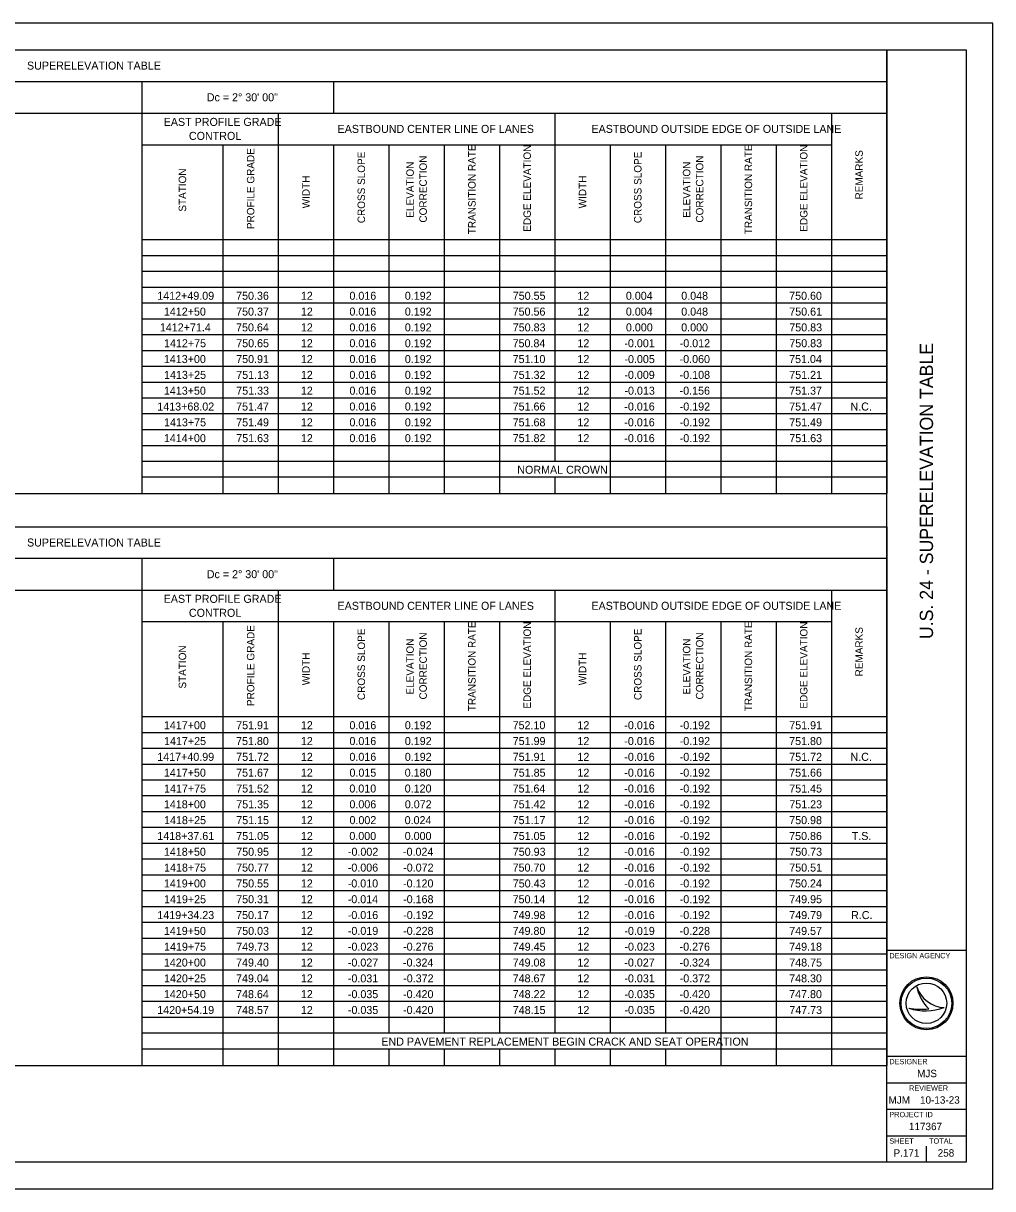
# Model space of a CAD drawing. Extents: x 0 to 34, y 0 to 22.
# Drawn here: x 15.71 to 34, y 0 to 22 of the extents above; entities that cross this region are included whole.
import ezdxf

# ---------------------------------------------------------------- set-up
doc = ezdxf.new("R2010")
doc.units = 0
for name, color, linetype in [('Default', 7, 'Continuous'), ('SH_Border', 7, 'Continuous'), ('SH_Cut_Line', 7, 'Continuous'), ('SH_Data', 7, 'Continuous')]:
    doc.layers.add(name, color=color, linetype=linetype)

msp = doc.modelspace()

# ---------------------------------------------------------------- linework, layer by layer
at = {"layer": 'Default'}
for p, q in [((1.5, 21.5), (32, 21.5)), ((32, 21.5), (32, 13.122)), ((1.5, 20.903), (32, 20.903)), ((17.947, 20.903), (17.947, 13.122)), ((21.564, 20.903), (21.564, 20.305)), ((1.5, 20.305), (32, 20.305)), ((20.521, 20.305), (20.521, 17.916)), ((25.739, 20.305), (25.739, 17.916)), ((30.956, 20.305), (30.956, 17.916)), ((17.947, 19.708), (30.956, 19.708)), ((19.477, 19.708), (19.477, 17.916)), ((21.564, 19.708), (21.564, 17.916)), ((22.608, 19.708), (22.608, 17.916)), ((23.651, 19.708), (23.651, 17.916)), ((24.695, 19.708), (24.695, 17.916)), ((26.782, 19.708), (26.782, 17.916)), ((27.826, 19.708), (27.826, 17.916)), ((28.869, 19.708), (28.869, 17.916)), ((29.913, 19.708), (29.913, 17.916)), ((17.947, 17.916), (32, 17.916)), ((19.477, 17.916), (19.477, 13.122)), ((20.521, 17.916), (20.521, 13.122)), ((21.564, 17.916), (21.564, 13.122)), ((22.608, 17.916), (22.608, 13.122)), ((23.651, 17.916), (23.651, 13.122)), ((24.695, 17.916), (24.695, 13.122)), ((25.739, 17.916), (25.739, 13.735)), ((26.782, 17.916), (26.782, 13.122)), ((27.826, 17.916), (27.826, 13.122)), ((28.869, 17.916), (28.869, 13.122)), ((29.913, 17.916), (29.913, 13.122)), ((30.956, 17.916), (30.956, 13.122)), ((17.947, 17.617), (32, 17.617)), ((17.947, 17.319), (32, 17.319)), ((17.947, 17.02), (32, 17.02)), ((17.947, 16.721), (32, 16.721)), ((17.947, 16.423), (32, 16.423)), ((17.947, 16.124), (32, 16.124)), ((17.947, 15.825), (32, 15.825)), ((17.947, 15.527), (32, 15.527)), ((17.947, 15.228), (32, 15.228)), ((17.947, 14.929), (32, 14.929)), ((17.947, 14.631), (32, 14.631)), ((17.947, 14.332), (32, 14.332)), ((17.947, 14.033), (32, 14.033)), ((17.947, 13.735), (32, 13.735)), ((17.947, 13.436), (32, 13.436)), ((25.739, 13.436), (25.739, 13.122)), ((1.5, 13.122), (32, 13.122)), ((1.5, 12.497), (32, 12.497)), ((32, 12.497), (32, 2.327)), ((1.5, 11.9), (32, 11.9)), ((17.947, 11.9), (17.947, 2.327)), ((21.564, 11.9), (21.564, 11.302)), ((1.5, 11.302), (32, 11.302)), ((20.521, 11.302), (20.521, 8.913)), ((25.739, 11.302), (25.739, 8.913)), ((30.956, 11.302), (30.956, 8.913)), ((17.947, 10.705), (30.956, 10.705)), ((19.477, 10.705), (19.477, 8.913)), ((21.564, 10.705), (21.564, 8.913)), ((22.608, 10.705), (22.608, 8.913)), ((23.651, 10.705), (23.651, 8.913)), ((24.695, 10.705), (24.695, 8.913)), ((26.782, 10.705), (26.782, 8.913)), ((27.826, 10.705), (27.826, 8.913)), ((28.869, 10.705), (28.869, 8.913)), ((29.913, 10.705), (29.913, 8.913)), ((17.947, 8.913), (32, 8.913)), ((19.477, 8.913), (19.477, 2.327)), ((20.521, 8.913), (20.521, 2.327)), ((21.564, 8.913), (21.564, 2.327)), ((22.608, 8.913), (22.608, 2.94)), ((23.651, 8.913), (23.651, 2.94)), ((24.695, 8.913), (24.695, 2.94)), ((25.739, 8.913), (25.739, 2.94)), ((26.782, 8.913), (26.782, 2.94)), ((27.826, 8.913), (27.826, 2.94)), ((28.869, 8.913), (28.869, 2.327)), ((29.913, 8.913), (29.913, 2.327)), ((30.956, 8.913), (30.956, 2.327)), ((17.947, 8.614), (32, 8.614)), ((17.947, 8.316), (32, 8.316)), ((17.947, 8.017), (32, 8.017)), ((17.947, 7.718), (32, 7.718)), ((17.947, 7.42), (32, 7.42)), ((17.947, 7.121), (32, 7.121)), ((17.947, 6.822), (32, 6.822)), ((17.947, 6.524), (32, 6.524)), ((17.947, 6.225), (32, 6.225)), ((17.947, 5.926), (32, 5.926)), ((17.947, 5.628), (32, 5.628)), ((17.947, 5.329), (32, 5.329)), ((17.947, 5.03), (32, 5.03)), ((17.947, 4.732), (32, 4.732)), ((17.947, 4.433), (32, 4.433)), ((17.947, 4.134), (32, 4.134)), ((17.947, 3.836), (32, 3.836)), ((17.947, 3.537), (32, 3.537)), ((17.947, 3.238), (32, 3.238)), ((17.947, 2.94), (32, 2.94)), ((17.947, 2.641), (32, 2.641)), ((22.608, 2.641), (22.608, 2.327)), ((23.651, 2.641), (23.651, 2.327)), ((24.695, 2.641), (24.695, 2.327)), ((25.739, 2.641), (25.739, 2.327)), ((26.782, 2.641), (26.782, 2.327)), ((27.826, 2.641), (27.826, 2.327)), ((1.5, 2.327), (32, 2.327))]:
    msp.add_line(p, q, dxfattribs=at)
at = {"layer": 'SH_Border'}
for p, q in [((32, 0.5), (32, 21.5)), ((32, 4.5), (33.5, 4.5)), ((32, 2.5), (33.5, 2.5)), ((32, 2), (33.5, 2)), ((32, 1.5), (33.5, 1.5)), ((32, 1), (33.5, 1))]:
    msp.add_line(p, q, dxfattribs=at)
msp.add_lwpolyline([(1.5, 21.5), (33.5, 21.5), (33.5, 0.5), (1.5, 0.5)], close=True, dxfattribs=at)
at = {"layer": 'SH_Cut_Line'}
msp.add_lwpolyline([(0, 0), (34, 0), (34, 22), (0, 22)], close=True, dxfattribs=at)
at = {"layer": 'SH_Data'}
for p, q in [((32.567, 3.81), (32.567, 3.81)), ((32.417, 3.41), (32.417, 3.41)), ((32.75, 3.5), (32.75, 3.5)), ((33.087, 3.419), (33.087, 3.419)), ((32.375, 0.675), (32.375, 0.675)), ((32.75, 0.5), (32.75, 0.8))]:
    msp.add_line(p, q, dxfattribs=at)
for radius in [0.5, 0.477, 0.477, 0.382]:
    msp.add_circle((32.75, 3.5), radius, dxfattribs=at)
for centre, radius, start, end in [((33.116, 3.998), 0.58, 198.9257, 198.9319), ((33.347, 3.97), 0.796, 191.6379, 191.6421), ((33.116, 3.998), 0.58, 198.9319, 267.1657), ((33.347, 3.97), 0.796, 191.6421, 226.0947), ((32.739, 4.37), 1.013, 251.4576, 290.0832), ((32.648, 4.654), 1.266, 259.4964, 259.4995), ((32.739, 4.37), 1.013, 251.4527, 251.4576), ((32.648, 4.654), 1.266, 259.4995, 276.6672)]:
    msp.add_arc(centre, radius, start, end, dxfattribs=at)

# ---------------------------------------------------------------- texts
at = {"layer": 'Default'}
for s, height, p in [('SUPERELEVATION TABLE', 0.15112, (15.779, 21.126)), ('Dc = 2° 30\' 00"', 0.15112, (19.171, 20.528)), ('EAST PROFILE GRADE ', 0.15112, (18.358, 20.063)), ('EASTBOUND CENTER LINE OF LANES', 0.15112, (21.639, 19.931)), ('EASTBOUND OUTSIDE EDGE OF OUTSIDE LANE', 0.15112, (26.429, 19.931)), ('CONTROL', 0.1511, (18.834, 19.799)), ('1412+49.09', 0.1511, (18.237, 16.781)), ('750.36', 0.1511, (19.725, 16.781)), ('12', 0.1511, (20.947, 16.781)), ('0.016', 0.1511, (21.863, 16.781)), ('0.192', 0.1511, (22.908, 16.781)), ('750.55', 0.1511, (24.945, 16.781)), ('12', 0.1511, (26.165, 16.781)), ('0.004', 0.1511, (27.079, 16.781)), ('0.048', 0.1511, (28.124, 16.781)), ('750.60', 0.1511, (30.16, 16.781)), ('1412+50', 0.1511, (18.362, 16.482)), ('750.37', 0.1511, (19.725, 16.482)), ('12', 0.1511, (20.947, 16.482)), ('0.016', 0.1511, (21.863, 16.482)), ('0.192', 0.1511, (22.908, 16.482)), ('750.56', 0.1511, (24.943, 16.482)), ('12', 0.1511, (26.165, 16.482)), ('0.004', 0.1511, (27.079, 16.482)), ('0.048', 0.1511, (28.124, 16.482)), ('750.61', 0.1511, (30.162, 16.482)), ('1412+71.4', 0.1511, (18.286, 16.184)), ('750.64', 0.1511, (19.724, 16.184)), ('12', 0.1511, (20.947, 16.184)), ('0.016', 0.1511, (21.863, 16.184)), ('0.192', 0.1511, (22.908, 16.184)), ('750.83', 0.1511, (24.945, 16.184)), ('12', 0.1511, (26.165, 16.184)), ('0.000', 0.1511, (27.08, 16.184)), ('0.000', 0.1511, (28.123, 16.184)), ('750.83', 0.1511, (30.163, 16.184)), ('1412+75', 0.1511, (18.365, 15.885)), ('750.65', 0.1511, (19.727, 15.885)), ('12', 0.1511, (20.947, 15.885)), ('0.016', 0.1511, (21.863, 15.885)), ('0.192', 0.1511, (22.908, 15.885)), ('750.84', 0.1511, (24.942, 15.885)), ('12', 0.1511, (26.165, 15.885)), ('-0.001', 0.1511, (27.051, 15.885)), ('-0.012', 0.1511, (28.095, 15.885)), ('750.83', 0.1511, (30.163, 15.885)), ('1413+00', 0.1511, (18.362, 15.586)), ('750.91', 0.1511, (19.726, 15.586)), ('12', 0.1511, (20.947, 15.586)), ('0.016', 0.1511, (21.863, 15.586)), ('0.192', 0.1511, (22.908, 15.586)), ('751.10', 0.1511, (24.942, 15.586)), ('12', 0.1511, (26.165, 15.586)), ('-0.005', 0.1511, (27.052, 15.586)), ('-0.060', 0.1511, (28.093, 15.586)), ('751.04', 0.1511, (30.159, 15.586)), ('1413+25', 0.1511, (18.365, 15.288)), ('751.13', 0.1511, (19.727, 15.288)), ('12', 0.1511, (20.947, 15.288)), ('0.016', 0.1511, (21.863, 15.288)), ('0.192', 0.1511, (22.908, 15.288)), ('751.32', 0.1511, (24.944, 15.288)), ('12', 0.1511, (26.165, 15.288)), ('-0.009', 0.1511, (27.051, 15.288)), ('-0.108', 0.1511, (28.094, 15.288)), ('751.21', 0.1511, (30.162, 15.288)), ('1413+50', 0.1511, (18.362, 14.989)), ('751.33', 0.1511, (19.727, 14.989)), ('12', 0.1511, (20.947, 14.989)), ('0.016', 0.1511, (21.863, 14.989)), ('0.192', 0.1511, (22.908, 14.989)), ('751.52', 0.1511, (24.944, 14.989)), ('12', 0.1511, (26.165, 14.989)), ('-0.013', 0.1511, (27.052, 14.989)), ('-0.156', 0.1511, (28.093, 14.989)), ('751.37', 0.1511, (30.161, 14.989)), ('1413+68.02', 0.1511, (18.238, 14.69)), ('751.47', 0.1511, (19.725, 14.69)), ('12', 0.1511, (20.947, 14.69)), ('0.016', 0.1511, (21.863, 14.69)), ('0.192', 0.1511, (22.908, 14.69)), ('751.66', 0.1511, (24.943, 14.69)), ('12', 0.1511, (26.165, 14.69)), ('-0.016', 0.1511, (27.05, 14.69)), ('-0.192', 0.1511, (28.095, 14.69)), ('751.47', 0.1511, (30.161, 14.69)), ('N.C.', 0.1511, (31.317, 14.69)), ('1413+75', 0.1511, (18.365, 14.392)), ('751.49', 0.1511, (19.726, 14.392)), ('12', 0.1511, (20.947, 14.392)), ('0.016', 0.1511, (21.863, 14.392)), ('0.192', 0.1511, (22.908, 14.392)), ('751.68', 0.1511, (24.943, 14.392)), ('12', 0.1511, (26.165, 14.392)), ('-0.016', 0.1511, (27.05, 14.392)), ('-0.192', 0.1511, (28.095, 14.392)), ('751.49', 0.1511, (30.162, 14.392)), ('1414+00', 0.1511, (18.362, 14.093)), ('751.63', 0.1511, (19.727, 14.093)), ('12', 0.1511, (20.947, 14.093)), ('0.016', 0.1511, (21.863, 14.093)), ('0.192', 0.1511, (22.908, 14.093)), ('751.82', 0.1511, (24.944, 14.093)), ('12', 0.1511, (26.165, 14.093)), ('-0.016', 0.1511, (27.05, 14.093)), ('-0.192', 0.1511, (28.095, 14.093)), ('751.63', 0.1511, (30.163, 14.093)), ('NORMAL CROWN', 0.15112, (25.03, 13.496)), ('SUPERELEVATION TABLE', 0.15112, (15.779, 12.123)), ('Dc = 2° 30\' 00"', 0.15112, (19.171, 11.525)), ('EAST PROFILE GRADE ', 0.15112, (18.358, 11.06)), ('EASTBOUND CENTER LINE OF LANES', 0.15112, (21.639, 10.928)), ('EASTBOUND OUTSIDE EDGE OF OUTSIDE LANE', 0.15112, (26.429, 10.928)), ('CONTROL', 0.1511, (18.834, 10.796)), ('1417+00', 0.1511, (18.362, 8.674)), ('751.91', 0.1511, (19.726, 8.674)), ('12', 0.1511, (20.947, 8.674)), ('0.016', 0.1511, (21.863, 8.674)), ('0.192', 0.1511, (22.908, 8.674)), ('752.10', 0.1511, (24.942, 8.674)), ('12', 0.1511, (26.165, 8.674)), ('-0.016', 0.1511, (27.05, 8.674)), ('-0.192', 0.1511, (28.095, 8.674)), ('751.91', 0.1511, (30.162, 8.674)), ('1417+25', 0.1511, (18.365, 8.375)), ('751.80', 0.1511, (19.724, 8.375)), ('12', 0.1511, (20.947, 8.375)), ('0.016', 0.1511, (21.863, 8.375)), ('0.192', 0.1511, (22.908, 8.375)), ('751.99', 0.1511, (24.944, 8.375)), ('12', 0.1511, (26.165, 8.375)), ('-0.016', 0.1511, (27.05, 8.375)), ('-0.192', 0.1511, (28.095, 8.375)), ('751.80', 0.1511, (30.16, 8.375)), ('1417+40.99', 0.1511, (18.237, 8.077)), ('751.72', 0.1511, (19.726, 8.077)), ('12', 0.1511, (20.947, 8.077)), ('0.016', 0.1511, (21.863, 8.077)), ('0.192', 0.1511, (22.908, 8.077)), ('751.91', 0.1511, (24.944, 8.077)), ('12', 0.1511, (26.165, 8.077)), ('-0.016', 0.1511, (27.05, 8.077)), ('-0.192', 0.1511, (28.095, 8.077)), ('751.72', 0.1511, (30.162, 8.077)), ('N.C.', 0.1511, (31.317, 8.077)), ('1417+50', 0.1511, (18.362, 7.778)), ('751.67', 0.1511, (19.725, 7.778)), ('12', 0.1511, (20.947, 7.778)), ('0.015', 0.1511, (21.864, 7.778)), ('0.180', 0.1511, (22.906, 7.778)), ('751.85', 0.1511, (24.945, 7.778)), ('12', 0.1511, (26.165, 7.778)), ('-0.016', 0.1511, (27.05, 7.778)), ('-0.192', 0.1511, (28.095, 7.778)), ('751.66', 0.1511, (30.16, 7.778)), ('1417+75', 0.1511, (18.365, 7.479)), ('751.52', 0.1511, (19.726, 7.479)), ('12', 0.1511, (20.947, 7.479)), ('0.010', 0.1511, (21.862, 7.479)), ('0.120', 0.1511, (22.906, 7.479)), ('751.64', 0.1511, (24.942, 7.479)), ('12', 0.1511, (26.165, 7.479)), ('-0.016', 0.1511, (27.05, 7.479)), ('-0.192', 0.1511, (28.095, 7.479)), ('751.45', 0.1511, (30.162, 7.479)), ('1418+00', 0.1511, (18.362, 7.181)), ('751.35', 0.1511, (19.727, 7.181)), ('12', 0.1511, (20.947, 7.181)), ('0.006', 0.1511, (21.863, 7.181)), ('0.072', 0.1511, (22.908, 7.181)), ('751.42', 0.1511, (24.944, 7.181)), ('12', 0.1511, (26.165, 7.181)), ('-0.016', 0.1511, (27.05, 7.181)), ('-0.192', 0.1511, (28.095, 7.181)), ('751.23', 0.1511, (30.163, 7.181)), ('1418+25', 0.1511, (18.365, 6.882)), ('751.15', 0.1511, (19.727, 6.882)), ('12', 0.1511, (20.947, 6.882)), ('0.002', 0.1511, (21.864, 6.882)), ('0.024', 0.1511, (22.905, 6.882)), ('751.17', 0.1511, (24.943, 6.882)), ('12', 0.1511, (26.165, 6.882)), ('-0.016', 0.1511, (27.05, 6.882)), ('-0.192', 0.1511, (28.095, 6.882)), ('750.98', 0.1511, (30.161, 6.882)), ('1418+37.61', 0.1511, (18.238, 6.583)), ('751.05', 0.1511, (19.727, 6.583)), ('12', 0.1511, (20.947, 6.583)), ('0.000', 0.1511, (21.862, 6.583)), ('0.000', 0.1511, (22.906, 6.583)), ('751.05', 0.1511, (24.945, 6.583)), ('12', 0.1511, (26.165, 6.583)), ('-0.016', 0.1511, (27.05, 6.583)), ('-0.192', 0.1511, (28.095, 6.583)), ('750.86', 0.1511, (30.16, 6.583)), ('T.S.', 0.1511, (31.341, 6.583)), ('1418+50', 0.1511, (18.362, 6.285)), ('750.95', 0.1511, (19.727, 6.285)), ('12', 0.1511, (20.947, 6.285)), ('-0.002', 0.1511, (21.834, 6.285)), ('-0.024', 0.1511, (22.874, 6.285)), ('750.93', 0.1511, (24.945, 6.285)), ('12', 0.1511, (26.165, 6.285)), ('-0.016', 0.1511, (27.05, 6.285)), ('-0.192', 0.1511, (28.095, 6.285)), ('750.73', 0.1511, (30.163, 6.285)), ('1418+75', 0.1511, (18.365, 5.986)), ('750.77', 0.1511, (19.725, 5.986)), ('12', 0.1511, (20.947, 5.986)), ('-0.006', 0.1511, (21.832, 5.986)), ('-0.072', 0.1511, (22.877, 5.986)), ('750.70', 0.1511, (24.942, 5.986)), ('12', 0.1511, (26.165, 5.986)), ('-0.016', 0.1511, (27.05, 5.986)), ('-0.192', 0.1511, (28.095, 5.986)), ('750.51', 0.1511, (30.162, 5.986)), ('1419+00', 0.1511, (18.362, 5.687)), ('750.55', 0.1511, (19.727, 5.687)), ('12', 0.1511, (20.947, 5.687)), ('-0.010', 0.1511, (21.831, 5.687)), ('-0.120', 0.1511, (22.875, 5.687)), ('750.43', 0.1511, (24.945, 5.687)), ('12', 0.1511, (26.165, 5.687)), ('-0.016', 0.1511, (27.05, 5.687)), ('-0.192', 0.1511, (28.095, 5.687)), ('750.24', 0.1511, (30.159, 5.687)), ('1419+25', 0.1511, (18.365, 5.389)), ('750.31', 0.1511, (19.726, 5.389)), ('12', 0.1511, (20.947, 5.389)), ('-0.014', 0.1511, (21.831, 5.389)), ('-0.168', 0.1511, (22.876, 5.389)), ('750.14', 0.1511, (24.942, 5.389)), ('12', 0.1511, (26.165, 5.389)), ('-0.016', 0.1511, (27.05, 5.389)), ('-0.192', 0.1511, (28.095, 5.389)), ('749.95', 0.1511, (30.162, 5.389)), ('1419+34.23', 0.1511, (18.238, 5.09)), ('750.17', 0.1511, (19.725, 5.09)), ('12', 0.1511, (20.947, 5.09)), ('-0.016', 0.1511, (21.832, 5.09)), ('-0.192', 0.1511, (22.877, 5.09)), ('749.98', 0.1511, (24.943, 5.09)), ('12', 0.1511, (26.165, 5.09)), ('-0.016', 0.1511, (27.05, 5.09)), ('-0.192', 0.1511, (28.095, 5.09)), ('749.79', 0.1511, (30.162, 5.09)), ('R.C.', 0.1511, (31.328, 5.09)), ('1419+50', 0.1511, (18.362, 4.791)), ('750.03', 0.1511, (19.727, 4.791)), ('12', 0.1511, (20.947, 4.791)), ('-0.019', 0.1511, (21.833, 4.791)), ('-0.228', 0.1511, (22.876, 4.791)), ('749.80', 0.1511, (24.942, 4.791)), ('12', 0.1511, (26.165, 4.791)), ('-0.019', 0.1511, (27.051, 4.791)), ('-0.228', 0.1511, (28.094, 4.791)), ('749.57', 0.1511, (30.161, 4.791)), ('1419+75', 0.1511, (18.365, 4.493)), ('749.73', 0.1511, (19.727, 4.493)), ('12', 0.1511, (20.947, 4.493)), ('-0.023', 0.1511, (21.834, 4.493)), ('-0.276', 0.1511, (22.876, 4.493)), ('749.45', 0.1511, (24.945, 4.493)), ('12', 0.1511, (26.165, 4.493)), ('-0.023', 0.1511, (27.052, 4.493)), ('-0.276', 0.1511, (28.093, 4.493)), ('749.18', 0.1511, (30.161, 4.493)), ('1420+00', 0.1511, (18.362, 4.194)), ('749.40', 0.1511, (19.724, 4.194)), ('12', 0.1511, (20.947, 4.194)), ('-0.027', 0.1511, (21.833, 4.194)), ('-0.324', 0.1511, (22.874, 4.194)), ('749.08', 0.1511, (24.943, 4.194)), ('12', 0.1511, (26.165, 4.194)), ('-0.027', 0.1511, (27.05, 4.194)), ('-0.324', 0.1511, (28.092, 4.194)), ('748.75', 0.1511, (30.162, 4.194)), ('1420+25', 0.1511, (18.365, 3.895)), ('749.04', 0.1511, (19.724, 3.895)), ('12', 0.1511, (20.947, 3.895)), ('-0.031', 0.1511, (21.833, 3.895)), ('-0.372', 0.1511, (22.877, 3.895)), ('748.67', 0.1511, (24.943, 3.895)), ('12', 0.1511, (26.165, 3.895)), ('-0.031', 0.1511, (27.051, 3.895)), ('-0.372', 0.1511, (28.095, 3.895)), ('748.30', 0.1511, (30.16, 3.895)), ('1420+50', 0.1511, (18.362, 3.597)), ('748.64', 0.1511, (19.724, 3.597)), ('12', 0.1511, (20.947, 3.597)), ('-0.035', 0.1511, (21.834, 3.597)), ('-0.420', 0.1511, (22.875, 3.597)), ('748.22', 0.1511, (24.944, 3.597)), ('12', 0.1511, (26.165, 3.597)), ('-0.035', 0.1511, (27.052, 3.597)), ('-0.420', 0.1511, (28.093, 3.597)), ('747.80', 0.1511, (30.16, 3.597)), ('1420+54.19', 0.1511, (18.237, 3.298)), ('748.57', 0.1511, (19.725, 3.298)), ('12', 0.1511, (20.947, 3.298)), ('-0.035', 0.1511, (21.834, 3.298)), ('-0.420', 0.1511, (22.875, 3.298)), ('748.15', 0.1511, (24.945, 3.298)), ('12', 0.1511, (26.165, 3.298)), ('-0.035', 0.1511, (27.052, 3.298)), ('-0.420', 0.1511, (28.093, 3.298)), ('747.73', 0.1511, (30.163, 3.298)), ('END PAVEMENT REPLACEMENT BEGIN CRACK AND SEAT OPERATION', 0.15112, (22.465, 2.701))]:
    msp.add_text(s, height=height, dxfattribs=at).set_placement(p)
for s, height, p in [('PROFILE GRADE', 0.14081, (20.069, 18.115)), ('TRANSITION RATE', 0.14081, (24.244, 18.018)), ('EDGE ELEVATION', 0.14081, (25.287, 18.066)), ('TRANSITION RATE', 0.14081, (29.461, 18.018)), ('EDGE ELEVATION', 0.14081, (30.505, 18.066)), ('REMARKS', 0.1408, (31.549, 18.674)), ('CROSS SLOPE', 0.14081, (22.157, 18.227)), ('ELEVATION ', 0.1408, (23.077, 18.331)), ('CORRECTION', 0.1408, (23.323, 18.238)), ('CROSS SLOPE', 0.14081, (27.374, 18.227)), ('ELEVATION ', 0.1408, (28.295, 18.331)), ('CORRECTION', 0.1408, (28.541, 18.238)), ('STATION', 0.1408, (18.782, 18.444)), ('WIDTH', 0.1408, (21.113, 18.507)), ('WIDTH', 0.1408, (26.331, 18.507)), ('PROFILE GRADE', 0.14081, (20.069, 9.112)), ('CROSS SLOPE', 0.14081, (22.157, 9.224)), ('TRANSITION RATE', 0.14081, (24.244, 9.015)), ('EDGE ELEVATION', 0.14081, (25.287, 9.063)), ('CROSS SLOPE', 0.14081, (27.374, 9.224)), ('TRANSITION RATE', 0.14081, (29.461, 9.015)), ('EDGE ELEVATION', 0.14081, (30.505, 9.063)), ('REMARKS', 0.1408, (31.549, 9.671)), ('ELEVATION ', 0.1408, (23.077, 9.328)), ('CORRECTION', 0.1408, (23.323, 9.235)), ('ELEVATION ', 0.1408, (28.295, 9.328)), ('CORRECTION', 0.1408, (28.541, 9.235)), ('STATION', 0.1408, (18.782, 9.441)), ('WIDTH', 0.1408, (21.113, 9.504)), ('WIDTH', 0.1408, (26.331, 9.504))]:
    msp.add_text(s, height=height, rotation=90, dxfattribs=at).set_placement(p)
at = {"layer": 'SH_Data'}
msp.add_text('U.S. 24 - SUPERELEVATION TABLE', height=0.25, rotation=90, dxfattribs=at).set_placement((32.875, 10.375))
for s, height, p in [('DESIGN AGENCY', 0.1, (32.05, 4.35)), ('DESIGNER', 0.1, (32.05, 2.35)), ('MJS', 0.14, (32.574, 2.105)), ('REVIEWER', 0.1, (32.422, 1.85)), ('MJM', 0.14, (32.035, 1.605)), ('10-13-23', 0.14, (32.629, 1.605)), ('PROJECT ID', 0.1, (32.05, 1.35)), ('117367', 0.14, (32.42, 1.105)), ('SHEET', 0.1, (32.05, 0.85)), ('TOTAL', 0.1, (32.8, 0.85)), ('P.171', 0.14, (32.129, 0.605)), ('258', 0.14, (32.962, 0.605))]:
    msp.add_text(s, height=height, dxfattribs=at).set_placement(p)

doc.saveas('drawing.dxf')
